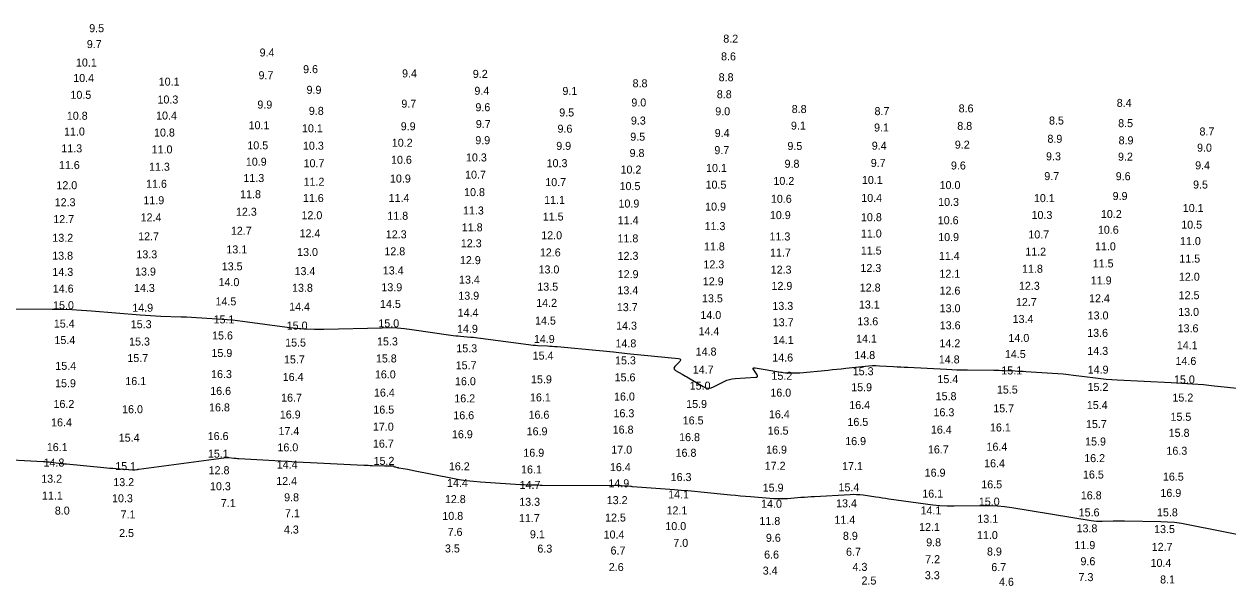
# Model space of a CAD drawing. Extents: x 988130 to 1132882, y 654656 to 841453.
# Drawn here: x 1034303 to 1035055, y 764496 to 764847 of the extents above; entities that cross this region are included whole.
import ezdxf

# ---------------------------------------------------------------- set-up
doc = ezdxf.new("R2010")
doc.units = 0
doc.layers.add('V-TOPO-MAJR', color=7, linetype='Continuous')
doc.layers.add('V-TOPO-SOUN', color=7, linetype='Continuous')

msp = doc.modelspace()

# ---------------------------------------------------------------- linework, layer by layer
at = {"layer": 'V-TOPO-MAJR'}
for points in [[(1034283.82, 764669.3), (1034320.78, 764669.04), (1034326.95, 764668.94), (1034333.11, 764668.72), (1034339.27, 764668.39), (1034345.42, 764667.94), (1034375.95, 764665.45), (1034379.14, 764665.2), (1034382.33, 764665), (1034385.53, 764664.83), (1034388.72, 764664.7), (1034401.52, 764664.23), (1034404.72, 764664.11), (1034407.91, 764663.96), (1034411.11, 764663.78), (1034414.3, 764663.59), (1034427.09, 764662.75), (1034430.29, 764662.52), (1034433.47, 764662.23), (1034436.66, 764661.88), (1034439.83, 764661.49), (1034467.69, 764657.76), (1034473.4, 764657.11), (1034479.11, 764656.69), (1034484.85, 764656.49), (1034490.59, 764656.52), (1034527.09, 764657.42), (1034531.71, 764657.44), (1034536.32, 764657.26), (1034540.91, 764656.89), (1034545.5, 764656.33), (1034569.9, 764652.8), (1034571.44, 764652.59), (1034572.98, 764652.4), (1034574.52, 764652.23), (1034576.07, 764652.08), (1034582.26, 764651.55), (1034583.81, 764651.4), (1034585.36, 764651.24), (1034586.9, 764651.06), (1034588.44, 764650.86), (1034618.39, 764646.87), (1034619.88, 764646.69), (1034621.37, 764646.54), (1034622.86, 764646.41), (1034624.35, 764646.32), (1034630.33, 764646.01), (1034631.82, 764645.93), (1034633.32, 764645.83), (1034634.81, 764645.71), (1034636.3, 764645.58), (1034662.93, 764643.06), (1034665.07, 764642.86), (1034667.21, 764642.65), (1034669.36, 764642.44), (1034671.5, 764642.23), (1034680.07, 764641.38), (1034682.21, 764641.16), (1034684.35, 764640.95), (1034686.49, 764640.73), (1034688.64, 764640.52), (1034712.28, 764638.1), (1034713.12, 764637.91), (1034713.51, 764637.55), (1034713.44, 764637.03), (1034712.93, 764636.34), (1034709.95, 764633.25), (1034709.42, 764632.51), (1034709.3, 764631.83), (1034709.61, 764631.22), (1034710.33, 764630.66), (1034714.47, 764628.33), (1034715.47, 764627.77), (1034716.46, 764627.2), (1034717.46, 764626.62), (1034718.45, 764626.04), (1034727.69, 764620.57), (1034729.28, 764619.85), (1034730.88, 764619.58), (1034732.5, 764619.76), (1034734.13, 764620.39), (1034740.67, 764623.79), (1034742.33, 764624.54), (1034744.04, 764625.11), (1034745.8, 764625.5), (1034747.61, 764625.69), (1034760.44, 764626.4), (1034761.16, 764626.54), (1034761.54, 764626.85), (1034761.57, 764627.34), (1034761.24, 764628), (1034759.24, 764631.01), (1034758.91, 764631.65), (1034758.93, 764632.07), (1034759.3, 764632.26), (1034760.02, 764632.23), (1034776.12, 764629.67), (1034779.11, 764629.29), (1034782.1, 764629.1), (1034785.09, 764629.1), (1034788.09, 764629.29), (1034805.61, 764630.92), (1034808.38, 764631.19), (1034811.15, 764631.46), (1034813.92, 764631.75), (1034816.68, 764632.05), (1034828.88, 764633.38), (1034831.08, 764633.57), (1034833.29, 764633.68), (1034835.5, 764633.69), (1034837.71, 764633.62), (1034846.56, 764633.13), (1034848.77, 764633.01), (1034850.99, 764632.89), (1034853.2, 764632.77), (1034855.41, 764632.66), (1034879.61, 764631.41), (1034882.89, 764631.25), (1034886.18, 764631.13), (1034889.46, 764631.05), (1034892.74, 764631), (1034909.1, 764630.83), (1034910.77, 764630.8), (1034912.45, 764630.77), (1034914.12, 764630.72), (1034915.79, 764630.66), (1034922.48, 764630.39), (1034924.15, 764630.32), (1034925.82, 764630.24), (1034927.5, 764630.15), (1034929.17, 764630.06), (1034945.8, 764629.09), (1034949.13, 764628.87), (1034952.45, 764628.58), (1034955.76, 764628.24), (1034959.07, 764627.84), (1034972.7, 764626.08), (1034976.08, 764625.67), (1034979.46, 764625.34), (1034982.85, 764625.07), (1034986.25, 764624.87), (1035019.94, 764623.21), (1035026.68, 764622.84), (1035033.42, 764622.37), (1035040.15, 764621.81), (1035046.87, 764621.16), (1035083.92, 764617.31)], [(1035070.52, 764526.17), (1035030.68, 764534.23), (1035026.4, 764534.99), (1035022.1, 764535.56), (1035017.78, 764535.93), (1035013.44, 764536.1), (1034990.79, 764536.47), (1034989.05, 764536.49), (1034987.31, 764536.5), (1034985.57, 764536.48), (1034983.84, 764536.45), (1034976.88, 764536.28), (1034975.15, 764536.28), (1034973.42, 764536.35), (1034971.69, 764536.51), (1034969.97, 764536.75), (1034920.4, 764544.77), (1034915.94, 764545.39), (1034911.47, 764545.83), (1034906.99, 764546.06), (1034902.49, 764546.11), (1034884.46, 764545.91), (1034879.96, 764545.95), (1034875.47, 764546.15), (1034870.99, 764546.53), (1034866.53, 764547.07), (1034843.56, 764550.32), (1034841.55, 764550.6), (1034839.54, 764550.89), (1034837.54, 764551.18), (1034835.53, 764551.47), (1034827.51, 764552.65), (1034825.5, 764552.89), (1034823.49, 764553.03), (1034821.47, 764553.07), (1034819.45, 764553), (1034797.19, 764551.73), (1034795.07, 764551.6), (1034792.95, 764551.47), (1034790.83, 764551.32), (1034788.71, 764551.17), (1034780.23, 764550.52), (1034778.11, 764550.4), (1034775.99, 764550.37), (1034773.87, 764550.41), (1034771.75, 764550.53), (1034757.16, 764551.66), (1034754.02, 764551.91), (1034750.89, 764552.18), (1034747.75, 764552.47), (1034744.62, 764552.77), (1034726.19, 764554.6), (1034722.08, 764554.99), (1034717.96, 764555.36), (1034713.84, 764555.71), (1034709.72, 764556.03), (1034683.5, 764557.98), (1034683.16, 764558.01), (1034682.82, 764558.04), (1034682.48, 764558.08), (1034682.14, 764558.13), (1034680.78, 764558.32), (1034680.44, 764558.37), (1034680.1, 764558.4), (1034679.76, 764558.42), (1034679.42, 764558.43), (1034676.64, 764558.48), (1034676.06, 764558.49), (1034675.48, 764558.49), (1034674.91, 764558.5), (1034674.33, 764558.5), (1034626.99, 764558.84), (1034625.86, 764558.85), (1034624.74, 764558.87), (1034623.61, 764558.89), (1034622.48, 764558.91), (1034617.98, 764559), (1034616.85, 764559.03), (1034615.73, 764559.08), (1034614.6, 764559.13), (1034613.48, 764559.2), (1034588.44, 764560.85), (1034584.02, 764561.21), (1034579.62, 764561.71), (1034575.25, 764562.36), (1034570.89, 764563.15), (1034546.72, 764567.92), (1034545.75, 764568.11), (1034544.79, 764568.3), (1034543.82, 764568.48), (1034542.85, 764568.67), (1034537.48, 764569.68), (1034537.26, 764569.72), (1034537.03, 764569.76), (1034536.81, 764569.81), (1034536.59, 764569.87), (1034535.5, 764570.13), (1034535.39, 764570.16), (1034535.28, 764570.2), (1034535.17, 764570.24), (1034535.06, 764570.28), (1034534.51, 764570.53), (1034534.46, 764570.56), (1034534.41, 764570.58), (1034534.35, 764570.61), (1034534.3, 764570.64), (1034534.1, 764570.75), (1034534.04, 764570.78), (1034533.99, 764570.8), (1034533.93, 764570.81), (1034533.88, 764570.82), (1034532.29, 764570.95), (1034532.25, 764570.96), (1034532.2, 764570.96), (1034532.15, 764570.96), (1034532.1, 764570.96), (1034531.91, 764570.94), (1034531.86, 764570.94), (1034531.81, 764570.94), (1034531.76, 764570.94), (1034531.71, 764570.93), (1034531.25, 764570.91), (1034531.15, 764570.91), (1034531.06, 764570.9), (1034530.96, 764570.9), (1034530.87, 764570.9), (1034529.5, 764570.87), (1034529.24, 764570.86), (1034528.98, 764570.86), (1034528.72, 764570.86), (1034528.46, 764570.87), (1034520.89, 764571.09), (1034519.54, 764571.13), (1034518.2, 764571.18), (1034516.85, 764571.24), (1034515.5, 764571.3), (1034482.28, 764572.97), (1034477.64, 764573.21), (1034473, 764573.45), (1034468.36, 764573.71), (1034463.72, 764573.97), (1034437.41, 764575.48), (1034436.65, 764575.53), (1034435.88, 764575.58), (1034435.11, 764575.64), (1034434.34, 764575.71), (1034431.28, 764575.99), (1034430.51, 764576.03), (1034429.75, 764576.04), (1034428.98, 764576), (1034428.22, 764575.92), (1034375.04, 764568.76), (1034374.72, 764568.72), (1034374.39, 764568.67), (1034374.07, 764568.62), (1034373.74, 764568.57), (1034372.44, 764568.36), (1034372.11, 764568.32), (1034371.79, 764568.3), (1034371.46, 764568.29), (1034371.13, 764568.31), (1034360.66, 764569.14), (1034358.8, 764569.29), (1034356.95, 764569.45), (1034355.09, 764569.62), (1034353.24, 764569.79), (1034329.86, 764572.01), (1034328.65, 764572.13), (1034327.44, 764572.26), (1034326.23, 764572.4), (1034325.03, 764572.55), (1034320.2, 764573.16), (1034318.99, 764573.31), (1034317.78, 764573.43), (1034316.57, 764573.52), (1034315.35, 764573.59), (1034284.07, 764575.17)]]:
    msp.add_lwpolyline(points, dxfattribs=at)

# ---------------------------------------------------------------- texts
at = {"layer": 'V-TOPO-SOUN'}
for s, p in [('9.5', (1034344.01, 764842.15)), ('8.2', (1034740.17, 764835.6)), ('9.7', (1034342.52, 764832.2)), ('10.1 ', (1034335.73, 764820.69)), ('9.4', (1034450.47, 764826.95)), ('8.6', (1034738.78, 764824.51)), ('9.7', (1034449.8, 764812.75)), ('9.6', (1034477.66, 764816.54)), ('9.4', (1034539.48, 764813.87)), ('9.2', (1034583.7, 764813.58)), ('10.4 ', (1034334.05, 764811.01)), ('10.1 ', (1034387.44, 764808.72)), ('8.8', (1034683.5, 764807.7)), ('8.8', (1034737.28, 764811.5)), ('10.5 ', (1034332.3, 764800.49)), ('10.3 ', (1034386.67, 764797.56)), ('9.9', (1034479.8, 764803.64)), ('9.4', (1034584.68, 764803.01)), ('9.1', (1034639.67, 764802.88)), ('8.8', (1034736.12, 764800.86)), ('9.9', (1034449.08, 764794.4)), ('9.8', (1034481.24, 764790.47)), ('9.7', (1034539.04, 764794.95)), ('9.6', (1034585.32, 764792.74)), ('9.5', (1034637.67, 764789.46)), ('9.0', (1034682.74, 764795.71)), ('9.0', (1034735.15, 764790.2)), ('8.8', (1034782.92, 764791.58)), ('8.7', (1034834.65, 764790.31)), ('8.6', (1034887.2, 764792)), ('8.4', (1034985.99, 764795.45)), ('10.8 ', (1034330.03, 764787.4)), ('10.4 ', (1034385.79, 764787.54)), ('9.7', (1034585.56, 764782.23)), ('9.3', (1034682.45, 764784.4)), ('8.5', (1034943.67, 764784.43)), ('8.5', (1034986.88, 764782.78)), ('11.0 ', (1034328.29, 764777.56)), ('10.8 ', (1034384.51, 764776.92)), ('10.1 ', (1034443.59, 764781.47)), ('10.1 ', (1034476.95, 764779.56)), ('9.9', (1034538.65, 764780.83)), ('9.6', (1034636.6, 764779.31)), ('9.4', (1034734.81, 764776.61)), ('9.1', (1034782.44, 764781.23)), ('9.1', (1034834.38, 764780.07)), ('8.8', (1034886.36, 764781.08)), ('8.7', (1035037.69, 764777.57)), ('11.3 ', (1034326.6, 764767.02)), ('10.5 ', (1034442.82, 764768.92)), ('10.3 ', (1034477.57, 764768.69)), ('10.2 ', (1034533.07, 764770.53)), ('9.9', (1034585.23, 764772.13)), ('9.9', (1034635.81, 764768.59)), ('9.5', (1034682.05, 764774.3)), ('9.5', (1034780.24, 764768.51)), ('9.4', (1034832.95, 764768.69)), ('9.2', (1034884.83, 764769.35)), ('8.9', (1034942.68, 764773)), ('8.9', (1034987.15, 764772.02)), ('9.0', (1035036.16, 764767.45)), ('11.0 ', (1034383.03, 764766.36)), ('10.6 ', (1034532.58, 764759.87)), ('10.3 ', (1034579.41, 764761.35)), ('9.8', (1034681.62, 764764.12)), ('9.7', (1034734.6, 764765.91)), ('9.3', (1034941.82, 764762.05)), ('9.2', (1034986.79, 764761.83)), ('11.6 ', (1034325.09, 764756.57)), ('11.3 ', (1034381.4, 764755.53)), ('10.9 ', (1034441.88, 764758.67)), ('10.7 ', (1034477.95, 764757.73)), ('10.3 ', (1034629.79, 764757.76)), ('10.2 ', (1034675.97, 764753.76)), ('10.1 ', (1034729.4, 764754.77)), ('9.8', (1034778.46, 764757.4)), ('9.7', (1034832.32, 764757.91)), ('9.6', (1034882.39, 764756.31)), ('9.4', (1035034.99, 764756.4)), ('11.6 ', (1034379.55, 764744.86)), ('11.3 ', (1034440.34, 764748.48)), ('11.2 ', (1034477.94, 764746.16)), ('10.9 ', (1034531.92, 764748.15)), ('10.7 ', (1034578.85, 764750.56)), ('10.7 ', (1034628.95, 764745.9)), ('10.5 ', (1034729.1, 764744.33)), ('10.2 ', (1034771.49, 764746.65)), ('10.1 ', (1034826.78, 764747.27)), ('9.7', (1034940.73, 764749.67)), ('9.6', (1034985.35, 764749.61)), ('9.5', (1035033.68, 764744.4)), ('12.0 ', (1034323.51, 764743.99)), ('11.8 ', (1034438.3, 764738.37)), ('10.8 ', (1034578.24, 764739.67)), ('10.5 ', (1034675.38, 764743.42)), ('10.0 ', (1034875.31, 764744.05)), ('9.9', (1034983.42, 764737.23)), ('12.3 ', (1034322.45, 764733.34)), ('11.9 ', (1034377.85, 764734.6)), ('11.6 ', (1034477.53, 764735.97)), ('11.4 ', (1034531.09, 764736.02)), ('11.1 ', (1034628.27, 764734.83)), ('10.9 ', (1034674.7, 764732.53)), ('10.9 ', (1034728.82, 764730.63)), ('10.6 ', (1034769.92, 764735.48)), ('10.4 ', (1034826.38, 764736.06)), ('10.3 ', (1034874.41, 764733.53)), ('10.1 ', (1034934.23, 764735.91)), ('10.1 ', (1035027.25, 764729.73)), ('12.7 ', (1034321.58, 764722.78)), ('12.4 ', (1034376.13, 764723.87)), ('12.3 ', (1034435.69, 764727.39)), ('12.0 ', (1034476.64, 764725.25)), ('11.8 ', (1034530.28, 764724.87)), ('11.3 ', (1034577.53, 764728.18)), ('11.5 ', (1034627.4, 764724.4)), ('11.4 ', (1034674.21, 764722.1)), ('10.9 ', (1034769.29, 764725.31)), ('10.8 ', (1034826.2, 764724)), ('10.6 ', (1034874.16, 764722.08)), ('10.3 ', (1034932.75, 764725.39)), ('10.2 ', (1034976.1, 764725.97)), ('12.7 ', (1034432.53, 764715.5)), ('11.8 ', (1034576.8, 764717.68)), ('11.3 ', (1034728.46, 764718.39)), ('10.6 ', (1034974.22, 764716.14)), ('10.5 ', (1035026.28, 764719.32)), ('13.2 ', (1034320.98, 764711.1)), ('12.7 ', (1034374.6, 764712.05)), ('12.4 ', (1034475.45, 764713.89)), ('12.3 ', (1034529.32, 764713.27)), ('12.3 ', (1034576.19, 764707.69)), ('12.0 ', (1034626.44, 764712.69)), ('11.8 ', (1034674.08, 764710.73)), ('11.3 ', (1034769.05, 764711.93)), ('11.0 ', (1034826.14, 764713.79)), ('10.9 ', (1034874.44, 764711.56)), ('10.7 ', (1034930.76, 764713.18)), ('11.0 ', (1035025.5, 764709.06)), ('13.8 ', (1034320.9, 764699.92)), ('13.3 ', (1034373.48, 764700.77)), ('13.1 ', (1034429.7, 764703.85)), ('13.0 ', (1034473.92, 764702.22)), ('12.8 ', (1034528.43, 764702.68)), ('12.6 ', (1034625.58, 764701.96)), ('12.3 ', (1034674.14, 764699.83)), ('11.8 ', (1034728.1, 764705.7)), ('11.7 ', (1034769.37, 764701.85)), ('11.5 ', (1034826.09, 764703.14)), ('11.4 ', (1034874.87, 764699.82)), ('11.2 ', (1034928.84, 764702.46)), ('11.0 ', (1034972.42, 764705.76)), ('13.5 ', (1034426.82, 764693.28)), ('12.9 ', (1034575.63, 764697.16)), ('12.3 ', (1034727.78, 764694.5)), ('12.3 ', (1034825.86, 764692.24)), ('11.8 ', (1034926.83, 764691.76)), ('11.5 ', (1034971, 764695.09)), ('11.5 ', (1035025.1, 764698.09)), ('14.3 ', (1034321.01, 764689.81)), ('13.9 ', (1034372.67, 764690.01)), ('13.4 ', (1034472.3, 764690.28)), ('13.4 ', (1034527.44, 764690.69)), ('13.4 ', (1034575.06, 764684.97)), ('13.0 ', (1034624.74, 764691.32)), ('12.9 ', (1034674.2, 764688.38)), ('12.3 ', (1034769.79, 764691.2)), ('12.1 ', (1034875.21, 764688.66)), ('11.9 ', (1034969.78, 764684.46)), ('12.0 ', (1035024.83, 764686.77)), ('14.6 ', (1034321.26, 764679.35)), ('14.3 ', (1034371.98, 764679.78)), ('14.0 ', (1034424.82, 764683.41)), ('13.8 ', (1034470.74, 764679.85)), ('13.9 ', (1034526.56, 764680.21)), ('13.5 ', (1034623.97, 764680.55)), ('13.4 ', (1034674.05, 764678.31)), ('12.9 ', (1034727.37, 764683.89)), ('12.9 ', (1034770.29, 764681.06)), ('12.8 ', (1034825.44, 764680.02)), ('12.6 ', (1034875.28, 764678.09)), ('12.3 ', (1034924.89, 764681.09)), ('14.5 ', (1034422.92, 764671.36)), ('14.5 ', (1034525.7, 764669.77)), ('13.9 ', (1034574.62, 764674.9)), ('14.2 ', (1034623.29, 764670.45)), ('13.5 ', (1034726.86, 764673.28)), ('13.1 ', (1034824.9, 764669.39)), ('12.7 ', (1034923.01, 764670.95)), ('12.4 ', (1034968.68, 764673.27)), ('12.5 ', (1035024.68, 764675.22)), ('15.0 ', (1034321.45, 764668.95)), ('14.9 ', (1034370.92, 764667.4)), ('14.4 ', (1034468.96, 764668.04)), ('14.4 ', (1034574.22, 764664.31)), ('13.7 ', (1034673.67, 764667.75)), ('14.0 ', (1034725.88, 764662.83)), ('13.3 ', (1034770.84, 764668.56)), ('13.0 ', (1034875.36, 764667.06)), ('13.0 ', (1034967.83, 764662.57)), ('13.0 ', (1035024.39, 764664.77)), ('15.4 ', (1034321.91, 764657.46)), ('15.3 ', (1034369.99, 764657.1)), ('15.1 ', (1034421.71, 764660.09)), ('15.0 ', (1034467.42, 764656.24)), ('15.0 ', (1034524.67, 764657.65)), ('14.9 ', (1034573.83, 764654.23)), ('14.5 ', (1034622.58, 764659.37)), ('14.3 ', (1034673.23, 764656.17)), ('13.7 ', (1034771.07, 764658.34)), ('13.6 ', (1034823.94, 764658.89)), ('13.6 ', (1034875.39, 764656.4)), ('13.4 ', (1034920.94, 764660.37)), ('13.6 ', (1035024.03, 764654.55)), ('15.4 ', (1034322.31, 764647.18)), ('15.6 ', (1034420.78, 764650.04)), ('14.9 ', (1034621.83, 764647.83)), ('14.4 ', (1034724.72, 764652.73)), ('14.1 ', (1034771.18, 764647.23)), ('14.1 ', (1034823.15, 764648.12)), ('14.0 ', (1034918.34, 764648.51)), ('13.6 ', (1034967.53, 764651.69)), ('15.3 ', (1034368.95, 764646.28)), ('15.9 ', (1034420.4, 764639.11)), ('15.5 ', (1034466.44, 764645.62)), ('15.3 ', (1034523.85, 764646.33)), ('15.3 ', (1034573.39, 764642.01)), ('14.8 ', (1034672.82, 764645.1)), ('14.8 ', (1034722.92, 764639.99)), ('14.2 ', (1034875.21, 764645.18)), ('14.3 ', (1034967.62, 764640.41)), ('14.1 ', (1035023.54, 764643.97)), ('15.7 ', (1034367.87, 764635.96)), ('15.7 ', (1034465.7, 764635.08)), ('15.8 ', (1034523.13, 764635.68)), ('15.4 ', (1034621.08, 764637.47)), ('15.3 ', (1034672.55, 764634.48)), ('14.6 ', (1034770.78, 764636.25)), ('14.8 ', (1034822.04, 764637.8)), ('14.8 ', (1034874.82, 764635.07)), ('14.5 ', (1034916.11, 764638.43)), ('14.6 ', (1035022.7, 764634.13)), ('15.4 ', (1034322.85, 764631.06)), ('16.3 ', (1034420.15, 764625.9)), ('16.4 ', (1034464.9, 764624.11)), ('16.0 ', (1034522.5, 764625.72)), ('15.7 ', (1034572.99, 764631.42)), ('15.6 ', (1034672.28, 764623.89)), ('14.7 ', (1034721.1, 764628.74)), ('15.2 ', (1034770.27, 764624.84)), ('15.3 ', (1034821.05, 764627.7)), ('15.1 ', (1034913.88, 764628.18)), ('14.9 ', (1034967.84, 764628.7)), ('15.9 ', (1034322.7, 764620.19)), ('16.1 ', (1034366.58, 764621.55)), ('16.0 ', (1034572.56, 764621.45)), ('15.9 ', (1034620.04, 764622.62)), ('15.0 ', (1034719.19, 764618.69)), ('15.9 ', (1034820.09, 764617.71)), ('15.4 ', (1034873.96, 764622.76)), ('15.2 ', (1034967.75, 764617.9)), ('15.0 ', (1035021.76, 764622.55)), ('16.6 ', (1034419.63, 764615.41)), ('16.7 ', (1034463.92, 764611.19)), ('16.4 ', (1034521.92, 764614.35)), ('16.2 ', (1034572.11, 764610.73)), ('16.1 ', (1034619.39, 764611.33)), ('16.0 ', (1034671.92, 764611.89)), ('16.0 ', (1034769.58, 764614.31)), ('15.8 ', (1034872.86, 764612.1)), ('15.5 ', (1034911.12, 764616.27)), ('15.2 ', (1035020.78, 764611.24)), ('16.2 ', (1034321.72, 764607.24)), ('16.0 ', (1034364.57, 764603.95)), ('16.8 ', (1034418.89, 764605.1)), ('16.5 ', (1034521.53, 764603.71)), ('16.3 ', (1034671.59, 764601.43)), ('15.9 ', (1034716.99, 764607.23)), ('16.4 ', (1034818.88, 764606.55)), ('16.3 ', (1034871.52, 764602.05)), ('15.7 ', (1034908.84, 764604.51)), ('15.4 ', (1034967.31, 764606.54)), ('16.4 ', (1034320.2, 764595.72)), ('16.9 ', (1034463.1, 764600.63)), ('16.6 ', (1034571.5, 764600.18)), ('16.6 ', (1034618.49, 764600.5)), ('16.5 ', (1034714.84, 764596.95)), ('16.4 ', (1034768.69, 764600.81)), ('16.5 ', (1034817.73, 764596.02)), ('15.7 ', (1034966.74, 764594.67)), ('15.5 ', (1035019.58, 764599.21)), ('16.6 ', (1034418.04, 764587.17)), ('17.4 ', (1034462.27, 764590.3)), ('17.0 ', (1034521.27, 764593.03)), ('16.9 ', (1034570.65, 764588.33)), ('16.9 ', (1034617.31, 764590.14)), ('16.8 ', (1034671.07, 764591.22)), ('16.8 ', (1034712.59, 764586.48)), ('16.5 ', (1034767.92, 764590.59)), ('16.4 ', (1034869.87, 764591.19)), ('16.1 ', (1034906.79, 764592.53)), ('15.8 ', (1035018.45, 764589.19)), ('16.1 ', (1034317.53, 764580.25)), ('15.4 ', (1034362.49, 764586.15)), ('16.0 ', (1034461.62, 764580.11)), ('16.7 ', (1034521.28, 764582.45)), ('16.9 ', (1034816.35, 764584.02)), ('16.7 ', (1034868.01, 764578.82)), ('16.4 ', (1034904.63, 764580.5)), ('15.9 ', (1034966.23, 764583.78)), ('15.1 ', (1034418.16, 764576.17)), ('15.2 ', (1034521.68, 764571.65)), ('16.9 ', (1034615.25, 764576.75)), ('17.0 ', (1034670.2, 764578.65)), ('16.8 ', (1034710.37, 764576.72)), ('16.9 ', (1034766.93, 764578.68)), ('16.2 ', (1034965.66, 764573.38)), ('16.3 ', (1035017.04, 764577.98)), ('14.8 ', (1034315.5, 764570.61)), ('15.1 ', (1034360.29, 764568.38)), ('12.8 ', (1034418.64, 764565.82)), ('14.4 ', (1034461.18, 764569.33)), ('16.2 ', (1034568.74, 764568.27)), ('16.1 ', (1034613.82, 764566.29)), ('16.4 ', (1034669.34, 764567.73)), ('17.2 ', (1034766.06, 764568.59)), ('17.1 ', (1034814.42, 764568.43)), ('16.9 ', (1034865.99, 764564.28)), ('16.4 ', (1034903.14, 764570.13)), ('13.2 ', (1034314.04, 764560.51)), ('13.2 ', (1034359.07, 764558.36)), ('12.4 ', (1034460.87, 764559.08)), ('14.4 ', (1034567.55, 764557.86)), ('14.7 ', (1034612.92, 764556.62)), ('14.9 ', (1034668.4, 764557.65)), ('16.3 ', (1034707.28, 764561.54)), ('16.5 ', (1034901.35, 764556.98)), ('16.5 ', (1034964.89, 764563.13)), ('16.5 ', (1035014.84, 764561.8)), ('11.1 ', (1034314.51, 764549.98)), ('10.3 ', (1034419.48, 764555.81)), ('9.8', (1034465.8, 764548.9)), ('14.1 ', (1034705.74, 764550.68)), ('15.9 ', (1034764.81, 764554.92)), ('15.4 ', (1034812.16, 764555.14)), ('16.1 ', (1034864.49, 764551.18)), ('16.8 ', (1034963.54, 764550.14)), ('16.9 ', (1035013.27, 764551.64)), ('10.3 ', (1034358.27, 764548.28)), ('7.1', (1034426.25, 764545.3)), ('12.8 ', (1034566.23, 764547.76)), ('13.3 ', (1034612.68, 764546.07)), ('13.2 ', (1034667.36, 764547.11)), ('14.0 ', (1034763.8, 764544.85)), ('13.4 ', (1034810.64, 764545.11)), ('15.0 ', (1034899.83, 764546.21)), ('8.0', (1034322.53, 764540.58)), ('7.1', (1034363.61, 764538.14)), ('7.1', (1034466.31, 764538.9)), ('10.8 ', (1034564.64, 764537.26)), ('11.7 ', (1034612.49, 764535.87)), ('12.5 ', (1034666.31, 764536.23)), ('12.1 ', (1034704.71, 764540.69)), ('11.8 ', (1034762.76, 764534.11)), ('11.4 ', (1034809.6, 764534.82)), ('14.1 ', (1034863.4, 764540.66)), ('13.1 ', (1034898.91, 764535.44)), ('15.6 ', (1034962.2, 764539.45)), ('15.8 ', (1035011.13, 764539.5)), ('2.5', (1034362.69, 764526.56)), ('4.3', (1034465.66, 764528.74)), ('7.6', (1034567.96, 764527.25)), ('10.0 ', (1034703.97, 764530.88)), ('12.1 ', (1034862.52, 764530.31)), ('13.8 ', (1034960.88, 764529.48)), ('13.5 ', (1035009.33, 764529.01)), ('9.1', (1034619.35, 764525.77)), ('10.4 ', (1034665.4, 764525.61)), ('7.0', (1034708.95, 764520.4)), ('9.6', (1034766.79, 764523.57)), ('8.9', (1034814.92, 764524.8)), ('9.8', (1034866.95, 764520.74)), ('11.0 ', (1034898.67, 764525.28)), ('11.9 ', (1034959.56, 764518.99)), ('3.5', (1034566.27, 764516.91)), ('6.3', (1034624.02, 764516.82)), ('6.7', (1034669.74, 764515.63)), ('6.6', (1034765.69, 764513.07)), ('6.7', (1034816.86, 764514.84)), ('8.9', (1034904.91, 764514.99)), ('12.7 ', (1035007.83, 764517.9)), ('2.6', (1034668.66, 764505.29)), ('4.3', (1034820.91, 764505.39)), ('7.2', (1034866.32, 764510.2)), ('6.7', (1034907.62, 764505.24)), ('9.6', (1034963.34, 764508.91)), ('10.4 ', (1035007.12, 764507.89)), ('3.4', (1034764.81, 764503.07)), ('2.5', (1034826.53, 764496.85)), ('3.3', (1034866.1, 764500.18)), ('4.6', (1034912.44, 764496.05)), ('7.3', (1034962.11, 764498.99)), ('8.1', (1035013.08, 764497.51))]:
    msp.add_text(s, height=5, rotation=360, dxfattribs=at).set_placement(p)

doc.saveas('drawing.dxf')
